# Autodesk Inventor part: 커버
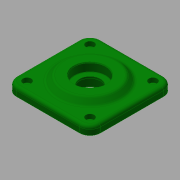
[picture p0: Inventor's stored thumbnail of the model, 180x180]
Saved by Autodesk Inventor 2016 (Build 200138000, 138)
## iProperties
Created: 2016-05
Part Number: 커버
Document SubType Name: Modeling
Designer: mduedu
Density: 2.71 g/cm^3
Material: 알루미늄 6061
Appearance: 진녹색
Author: mduedu
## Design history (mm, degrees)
sketch "스케치1"
  geometry: L1 (-40, -40)-(40, -40); L2 (40, -40)-(40, 40); L3 (40, 40)-(-40, 40); L4 (-40, 40)-(-40, -40); L5 (-40, -40)-(40, 40); L6 (40, -40)-(-40, 40); C1 r 25 at (0, 0); 1 further point
  constraints: 12 end point, 2 midpoint, 2 parallel, 1 centre point, 1 coincident, 1 horizontal, 1 perpendicular
  dimensions: "d30" = 50 diameter of C1; "d33" = 80 distance of L3.end L2.end; "d34" = 80 distance of L2.end L1.end
extrude "돌출1" new body sketch "스케치1" distance "d0" = 8; taper "d1" = 0 deg
fillet "모깎기4" dims "d35" = 10
extrude "돌출2" join sketch "스케치1" distance "d2" = 12; taper "d3" = 0 deg
sketch "스케치2"
  geometry: C1 r 30 at (0, 0); 1 further point
  constraints: 1 centre point, 1 coincident
  dimensions: "d4" = 60 diameter of C1
extrude "돌출3" join sketch "스케치2" distance "d5" = 5; taper "d6" = -45 deg
sketch "스케치3"
  geometry: L1 (30, -40)-(-30, -40) reference; L2 (40, 30)-(40, -30) reference; L3 (-30, 40)-(30, 40) reference; L4 (-40, -30)-(-40, 30) reference; C1 r 30 at (0, 0) reference; A1 r 10 centre (-30, -30) between (-40, -30) and (-30, -40) reference; A2 r 10 centre (30, -30) between (30, -40) and (40, -30) reference; A3 r 10 centre (30, 30) between (40, 30) and (30, 40) reference; A4 r 10 centre (-30, 30) between (-30, 40) and (-40, 30) reference; 4 further points
  constraints: 4 coincident
hole "구멍2" sketch "스케치3" at (-30, 30), (30, 30), (30, -30), (-30, -30) diameter "d36" = 4.5; stored, may be unused: countersink angle "d40" = 90 deg, drill point angle "d42" = 118 deg; dims "d37" = 6, "d38" = 8, "d39" = 4.4, "d41" = 8
fillet "모깎기1" dims "d14" = 3
fillet "모깎기5" dims "d43" = 3
sketch "스케치4"
  geometry: L1 (-23.757, 13)-(23.757, 13) reference; L2 (25, -12)-(-25, -12) reference; L3 (0, -12)-(0, 13); L4 (-20, -12)-(-20, 0); L5 (-20, 0)-(-15, 0); L6 (-15, 0)-(-15, 3); L7 (-15, 3)-(-10, 3); L8 (-10, 3)-(-10, 4.7); L9 (-10, 4.7)-(-15, 4.7); L10 (-15, 4.7)-(-15, 13); 1 further point
  constraints: 16 end point, 6 parallel, 2 midpoint, 2 point on line, 1 perpendicular
  dimensions: "d15" = 40 diameter of L4 L3; "d16" = 30 diameter of L10 L3; "d17" = 8.3 distance of L9.end L10.end; "d18" = 12 distance of L4.start L4.end; "d19" = 3 distance of L5.end L6.end; "d20" = 30 diameter of L6 L3; "d21" = 20 diameter of L8 L3
revolve "회전1" sketch "스케치4" stored, may be unused: angle "d22" = 90 deg
fillet "모깎기2" dims "d23" = 3
fillet "모깎기3" dims "d24" = 0.3
chamfer "모따기1" distance "d25" = 1; stored, may be unused: second distance "d26" = 2, angle "d27" = 45 deg
chamfer "모따기2" distance "d44" = 0.8; stored, may be unused: second distance "d45" = 2, angle "d46" = 30 deg
node "솔리드1"
node "투영된 루프1"
